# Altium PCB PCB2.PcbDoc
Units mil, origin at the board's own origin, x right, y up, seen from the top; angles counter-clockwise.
Board outline 6000 x 4000 mil, 2 copper layers (Top Layer, Bottom Layer); 1 components, 0 nets, 105 pads, 0 vias.
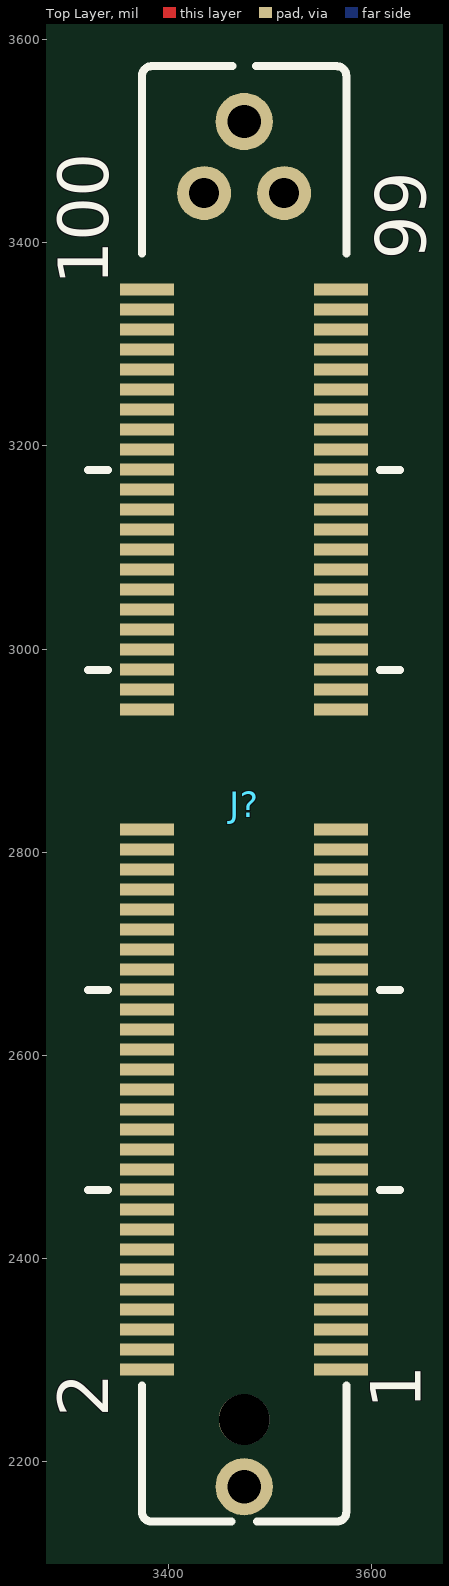
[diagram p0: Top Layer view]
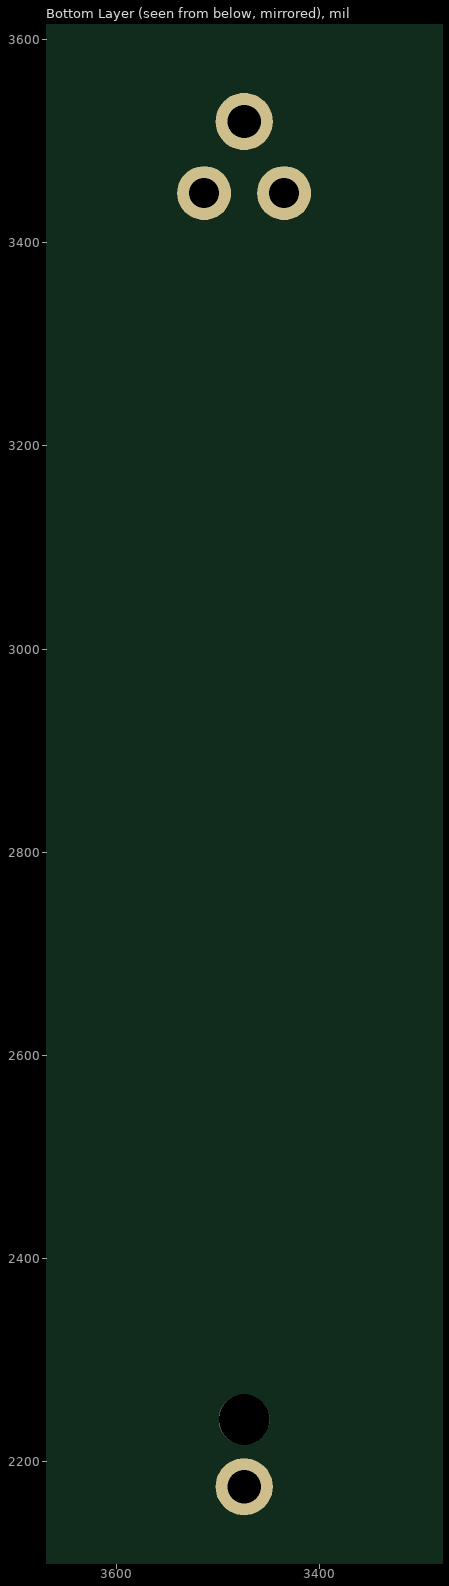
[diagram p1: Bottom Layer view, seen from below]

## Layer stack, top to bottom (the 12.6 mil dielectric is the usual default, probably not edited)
Top Solder: solder mask 0.4, Solder Resist, Dk 3.5
Top Layer: signal copper 1.4
Dielectric 1: dielectric 12.6, FR-4, Dk 4.8
Bottom Layer: signal copper 1.4
Bottom Solder: solder mask 0.4, Solder Resist, Dk 3.5

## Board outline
1000,1000 7000,1000 7000,5000 1000,5000

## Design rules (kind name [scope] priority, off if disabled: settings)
Clearance [All] p1: gap=10 ignorepadtopadclearanceinfootprint=FALSE
PolygonConnect [All] p1: connectstyle=Relief reliefconductorwidth=10 reliefentries=4 polygonreliefangle="90 Angle" airgapwidth=10
RoutingVias [All] p1: holewidth=28 width=50 viastyle="Through Hole" minholewidth=28 minwidth=50 maxholewidth=28 maxwidth=50
SolderMaskExpansion [All] p1: expansion=4 istentingtop=FALSE
Width [All] p1: maxlimit=10 minlimit=10 preferedwidth=10
30 further rules are at their usual default settings.

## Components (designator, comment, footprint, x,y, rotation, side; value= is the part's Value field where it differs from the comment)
J? "MEC5-050-01-L-DV-W1-K-TR" MEC5-050-01-L-DV-W1-K-TR 3474.53,2822.48 r90 top

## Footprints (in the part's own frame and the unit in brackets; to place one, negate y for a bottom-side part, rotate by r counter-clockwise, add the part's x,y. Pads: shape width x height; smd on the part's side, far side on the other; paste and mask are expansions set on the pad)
MEC5-050-01-L-DV-W1-K-TR [mm]
  rect 0.3x1.35 smd mask+0: 1(-13.5,-2.425) 2(-13.5,2.425) 3(-13,-2.425) 4(-13,2.425) 5(-12.5,-2.425) 6(-12.5,2.425) 7(-12,-2.425) 8(-12,2.425) 9(-11.5,-2.425) 10(-11.5,2.425) 11(-11,-2.425) 12(-11,2.425) 13(-10.5,-2.425) 14(-10.5,2.425) 15(-10,-2.425) 16(-10,2.425) 17(-9.5,-2.425) 18(-9.5,2.425) 19(-9,-2.425) 20(-9,2.425) 21(-8.5,-2.425) 22(-8.5,2.425) 23(-8,-2.425) 24(-8,2.425) 25(-7.5,-2.425) 26(-7.5,2.425) 27(-7,-2.425) 28(-7,2.425) 29(-6.5,-2.425) 30(-6.5,2.425) 31(-6,-2.425) 32(-6,2.425) 33(-5.5,-2.425) 34(-5.5,2.425) 35(-5,-2.425) 36(-5,2.425) 37(-4.5,-2.425) 38(-4.5,2.425) 39(-4,-2.425) 40(-4,2.425) 41(-3.5,-2.425) 42(-3.5,2.425) 43(-3,-2.425) 44(-3,2.425) 45(-2.5,-2.425) 46(-2.5,2.425) 47(-2,-2.425) 48(-2,2.425) 49(-1.5,-2.425) 50(-1.5,2.425) 51(-1,-2.425) 52(-1,2.425) 53(-0.5,-2.425) 54(-0.5,2.425) 55(0,-2.425) 56(0,2.425) 57(3,-2.425) 58(3,2.425) 59(3.5,-2.425) 60(3.5,2.425) 61(4,-2.425) 62(4,2.425) 63(4.5,-2.425) 64(4.5,2.425) 65(5,-2.425) 66(5,2.425) 67(5.5,-2.425) 68(5.5,2.425) 69(6,-2.425) 70(6,2.425) 71(6.5,-2.425) 72(6.5,2.425) 73(7,-2.425) 74(7,2.425) 75(7.5,-2.425) 76(7.5,2.425) 77(8,-2.425) 78(8,2.425) 79(8.5,-2.425) 80(8.5,2.425) 81(9,-2.425) 82(9,2.425) 83(9.5,-2.425) 84(9.5,2.425) 85(10,-2.425) 86(10,2.425) 87(10.5,-2.425) 88(10.5,2.425) 89(11,-2.425) 90(11,2.425) 91(11.5,-2.425) 92(11.5,2.425) 93(12,-2.425) 94(12,2.425) 95(12.5,-2.425) 96(12.5,2.425) 97(13,-2.425) 98(13,2.425) 99(13.5,-2.425) 100(13.5,2.425)
  round 1.43 hole 0.83 mask+0: G1(-16.43,0) G4(17.7,0)
  round 1.35 hole 0.75 mask+0: G2(15.91,1) G3(15.91,-1)
  round 1.27 hole 1.27 unplated: ""(-14.75,0)
  silkscreen extent -17.3,-3.9 19.08,3.9

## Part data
J?: package=None

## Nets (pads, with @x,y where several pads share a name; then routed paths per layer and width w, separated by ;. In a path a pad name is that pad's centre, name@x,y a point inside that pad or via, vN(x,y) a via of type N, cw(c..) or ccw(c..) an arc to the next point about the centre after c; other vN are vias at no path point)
pads on no net: J?. J?.1 J?.2 J?.3 J?.4 J?.5 J?.6 J?.7 J?.8 J?.9 J?.10 J?.11 J?.12 J?.13 J?.14 J?.15 J?.16 J?.17 J?.18 J?.19 J?.20 J?.21 J?.22 J?.23 J?.24 J?.25 J?.26 J?.27 J?.28 J?.29 J?.30 J?.31 J?.32 J?.33 J?.34 J?.35 J?.36 J?.37 J?.38 J?.39 J?.40 J?.41 J?.42 J?.43 J?.44 J?.45 J?.46 J?.47 J?.48 J?.49 J?.50 J?.51 J?.52 J?.53 J?.54 J?.55 J?.56 J?.57 J?.58 J?.59 J?.60 J?.61 J?.62 J?.63 J?.64 J?.65 J?.66 J?.67 J?.68 J?.69 J?.70 J?.71 J?.72 J?.73 J?.74 J?.75 J?.76 J?.77 J?.78 J?.79 J?.80 J?.81 J?.82 J?.83 J?.84 J?.85 J?.86 J?.87 J?.88 J?.89 J?.90 J?.91 J?.92 J?.93 J?.94 J?.95 J?.96 J?.97 J?.98 J?.99 J?.100 J?.G1 J?.G2 J?.G3 J?.G4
